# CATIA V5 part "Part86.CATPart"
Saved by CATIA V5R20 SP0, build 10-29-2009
Part number: FA 053000-3
Revision: ANY
Definition: UNKNOWN
Nomenclature: FA 053000-3
Source: Unknown
Bounding box of the stored display mesh (mm): x 0 to 2, y -1.45 to 1.45, z -1.45 to 1.45
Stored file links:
  C:\Users\Utente\Desktop\IO LAVORO\3D X SITO CF\CUMSA\3D files FA\FA 053012-21\Part86.CATPart

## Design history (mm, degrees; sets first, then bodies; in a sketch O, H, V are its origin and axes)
Body1 "Revolución1" (main body)
  Solid1: solid without history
